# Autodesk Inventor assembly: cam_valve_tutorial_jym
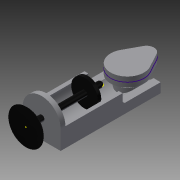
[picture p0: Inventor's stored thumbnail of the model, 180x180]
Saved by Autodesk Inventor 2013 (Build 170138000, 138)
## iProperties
Created: 2006-12
Part Number: cam_valve_tutorial_jym
Document SubType Name: Assembly
Designer: machilj
Mass: 106.08 g
Surface Area: 257.233 cm^2
Volume: 63.3377 cm^3
Density: 1.67482 g/cm^3
Author: machilj
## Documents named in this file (4)
- C:\Users\boganb\Documents\B2 Design\Goodyear\2013 Tutorial Files\Dynamic Simulation 3\cam_valve.iam
- C:\Users\boganb\Documents\B2 Design\Goodyear\2013 Tutorial Files\Dynamic Simulation 3\support.ipt
- C:\Users\boganb\Documents\B2 Design\Goodyear\2013 Tutorial Files\Dynamic Simulation 3\cam.ipt
- C:\Users\boganb\Documents\B2 Design\Goodyear\2013 Tutorial Files\Dynamic Simulation 3\valve.ipt
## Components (3 placed, 3 different names)
1. support:1 — Insert:1, Mate:1, Angle:1
2. cam:1 — Insert:1
3. valve:1 — Mate:1, Angle:1
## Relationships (3: Insert 1, Mate 1, Angle 1)
- Insert:1: support:1 ↔ cam:1
- Mate:1: support:1 ↔ valve:1
- Angle:1: support:1 ↔ valve:1
